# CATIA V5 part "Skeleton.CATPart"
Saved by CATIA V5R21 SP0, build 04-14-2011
Part number: Skeleton
Publications: "Mouse Main Sketch", "Top Surface", "Mouse Button Sketch01", "Mouse Button Sketch02", "Mouse Front Radius Value", "Mouse Rear Radius Value"
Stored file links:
  C:\CATIA V5_2015\ASD\Mouse Assembly Template\Skeleton.CATPart
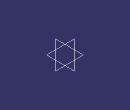
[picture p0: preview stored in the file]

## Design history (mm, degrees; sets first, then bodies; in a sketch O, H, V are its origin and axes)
Parameters
  `Mouse Front Length` = 60 mm
  `Mouse Front Radius Value` = 4 mm
  `Mouse Rear Radius Value` = 15 mm
Set1 "Reference Data"
  Point1 "Center Point": (0, 0, 0)
  Sketch1 "Mouse Main Sketch" on xy-plane, origin (0, 0, 0), H (1, 0, 0), V (0, 1, 0)
    arc A1 centre (-4, 0) radius 31 from (6.7229, 29.0864) to (-4, -31) ccw
    point P1 (-4, 0)
    line L1 (24.0179, 26) -> (45, 26)
    line L2 (60, 11) -> (60, -16)
    line L3 (45, -31) -> (-4, -31)
    arc A2 centre (45, 11) radius 15 from (45, 26) to (60, 11) cw
    arc A3 centre (45, -16) radius 15 from (60, -16) to (45, -31) cw
    arc A4 centre (24.0179, 76) radius 50 from (6.7229, 29.0864) to (24.0179, 26) ccw
    radius A1 = 31
    distance P1 V = 4
    distance V L2 = 60 {= `Mouse Front Length`}
    distance L3 L1 = 57
    radius A2 = 15
    radius A3 = 15 {= Sketch1.radius(A2)}
    radius A4 = 50
    coincidence: P1 H
    horizontal: L1 H, L3 H
    vertical: L2 V
    tangency: L3 A1, A2 L1, A2 L2, A3 L2, A3 L3, A4 A1, A4 L1
  Plane1 "YZ Offset Plane.1(Value=6.5mm)": type Offset, RefPlane yz-plane, Offset 6.5
  Sketch2 "Mouse Top Surface Profile" on Plane1, origin (6.5, 0, 0), H (0, 0, -1), V (0, 1, 0)
    arc A1 centre (75, 0) radius 100 from (-9.497, 53.4814) to (-12.0863, -49.1526) ccw
    point P1 (75, 0)
    radius A1 = 100
    distance V A1 = 25
    coincidence: P1 H
  Sketch3 "Mouse Top Surface Guide" on zx-plane, origin (0, 0, 0), H (1, 0, 0), V (0, 0, 1)
    point P1 (-34.4759, 10)
    arc A1 centre (6.5, -38.4675) radius 63.4675 from (-42.2102, 2.2196) to (28.8515, 20.934) cw
    arc A2 centre (81.6772, 161.3243) radius 150 from (28.8515, 20.934) to (79.4579, 11.3407) ccw
    point P5 (59.3187, 13)
    construction line L1 (-34.4759, 10) -> (-35, 0)
    point P6 (-35, 0)
    construction line L2 (59.3187, 13) -> (60, 0)
    point P7 (60, 0)
    construction line L3 (-34.4759, 10) -> (-34.4759, 0)
    point P8 (-34.4759, 0)
    construction line L4 (59.3187, 13) -> (59.3187, 0)
    point P9 (59.3187, 0)
    reference intersected point E1 (6.5, 25) from Sketch2.A1
    angle L3 L1 = 3
    angle L4 L2 = 3
    radius A2 = 150
    distance H A1 = 25
    distance P6 P7 = 95 {= `Mouse Front Length` + 35mm}
    distance V P7 = 60 {= `Mouse Front Length`}
    distance H P5 = 13
    distance H P1 = 10
    tangency: A2 A1
    coincidence: P6 H, P7 H, P8 H, P9 H, A1 E1, P5 A2, P1 A1
    vertical: L3 V, L4 V
  Sweep1 "Top Surface": type Unspec, Profile Sketch2, Guide Sketch3
  Sketch4 "Mouse Button Sketch01" on xy-plane, origin (0, 0, 0), H (1, 0, 0), V (0, 1, 0)
    arc A1 centre (75, 0) radius 50 from (46.7928, 41.2839) to (51.7121, -44.2456) ccw
    point P1 (75, 0)
    radius A1 = 50
    distance A1 V = 25
    coincidence: P1 H
  Sketch5 "Mouse Button Sketch02" on zx-plane, origin (0, 0, 0), H (1, 0, 0), V (0, 0, 1)
    line L1 (69.709, 3.2418) -> (19.3239, 12.1261)
    point P1 (59.738, 5)
    construction line L2 (59.738, 5) -> (60, 0)
    point P3 (60, 0)
    construction line L3 (60, 0) -> (60, 7.2196)
    angle L1 H = 10
    distance H P1 = 5
    distance P3 V = 60 {= `Mouse Front Length`}
    angle L3 L2 = 3
    coincidence: P3 H, P1 L1
    vertical: L3 V
Body1 (main body)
